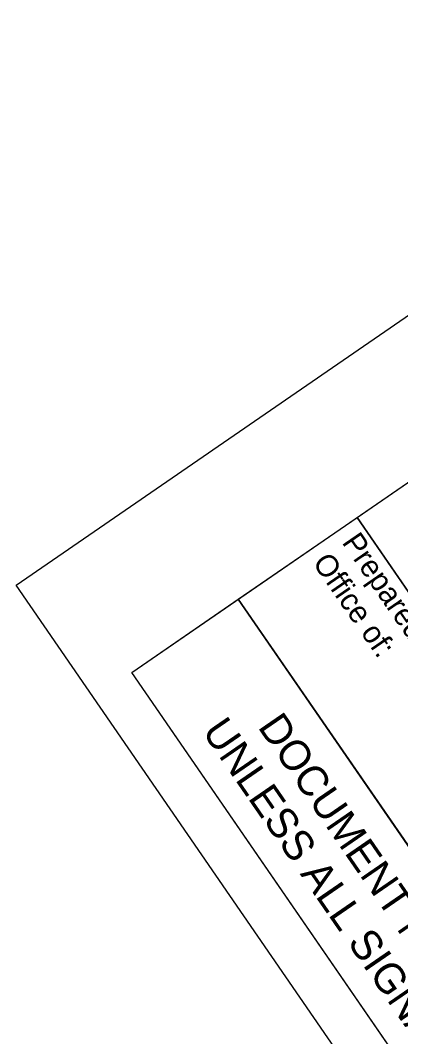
# Model space of a CAD drawing. Extents: x 2297526 to 2298642, y 599613 to 600819.
# Drawn here: x 2298445.3 to 2298486.8, y 599978.2 to 600089.1 of the extents above; entities that cross this region are included whole.
import ezdxf

# ---------------------------------------------------------------- set-up
doc = ezdxf.new("R2010")
doc.units = 0
for name, color, linetype in [('Exist DTM Drainline Cogo Elevation', 7, 'Continuous'), ('Exist Property Iron Pin Cogo Number', 7, 'Continuous'), ('Exist Roads Curbs Cogo Comment', 7, 'Continuous'), ('Exist Roads Curbs Cogo Number', 7, 'Continuous'), ('Exist Roads EOP Cogo Elevation', 7, 'Continuous'), ('Exist Roads EOP Other Cogo Point CELL', 7, 'Continuous')]:
    doc.layers.add(name, color=color, linetype=linetype)

msp = doc.modelspace()

# ---------------------------------------------------------------- linework, layer by layer
at = {"layer": 'Exist DTM Drainline Cogo Elevation'}
msp.add_lwpolyline([(2298537.65, 600073.14), (2298571.7, 600023.7), (2298516.11, 599985.42), (2298482.06, 600034.86)], close=True, dxfattribs=at)
at = {"layer": 'Exist Property Iron Pin Cogo Number'}
msp.add_lwpolyline([(2297647.43, 600347.7), (2298036.32, 599783), (2298066.14, 599803.53), (2298144.6, 599689.59), (2298480.39, 599975.84), (2298444.85, 600027.45), (2298522.99, 600081.26), (2298287.23, 600423.6), (2298114.33, 600674.66)], close=True, dxfattribs=at)
at = {"layer": 'Exist Roads Curbs Cogo Comment'}
for p, q in [((2298457.47, 600017.93), (2298469.09, 600025.93)), ((2298469.09, 600025.93), (2298537.16, 599927.08)), ((2298525.55, 599919.08), (2298457.47, 600017.93))]:
    msp.add_line(p, q, dxfattribs=at)
at = {"layer": 'Exist Roads Curbs Cogo Number'}
msp.add_lwpolyline([(2298113.82, 600728.3), (2297594.98, 600370.97), (2298105.44, 599629.74), (2298525.54, 599919.07), (2298457.47, 600017.93), (2298556.21, 600085.92)], close=True, dxfattribs=at)
at = {"layer": 'Exist Roads EOP Other Cogo Point CELL'}
msp.add_lwpolyline([(2298482.06, 600034.86), (2298550.12, 599936.03), (2298537.15, 599927.1), (2298469.09, 600025.93)], close=True, dxfattribs=at)

# ---------------------------------------------------------------- texts
at = {"layer": 'Exist Roads Curbs Cogo Comment'}
for s, p in [('DOCUMENT NOT CONSIDERED FINAL', (2298471.15, 600011.99)), ('UNLESS ALL SIGNATURES COMPLETED', (2298465.07, 600011.5))]:
    msp.add_text(s, height=3.3, rotation=304.5541, dxfattribs=at).set_placement(p)
at = {"layer": 'Exist Roads EOP Cogo Elevation'}
for s, p in [('Prepared in the ', (2298480.34, 600032.13)), ('Office of:', (2298477.13, 600029.92))]:
    msp.add_text(s, height=2.4, rotation=304.5541, dxfattribs=at).set_placement(p)

doc.saveas('drawing.dxf')
